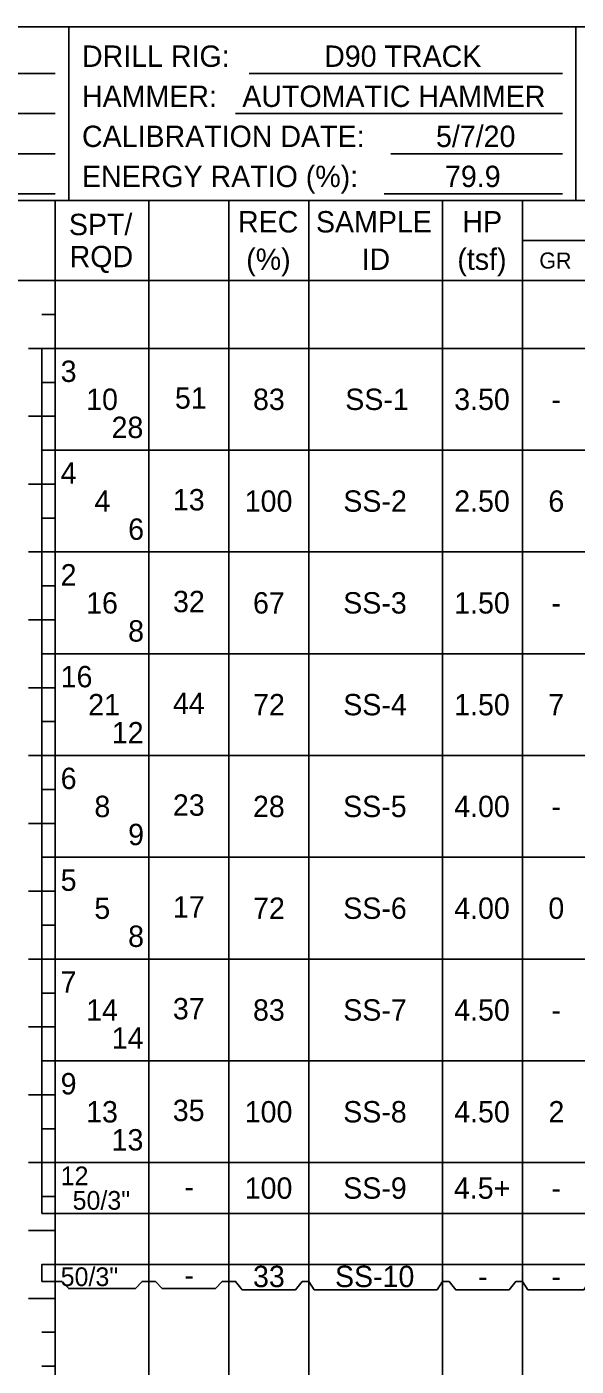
# Model space of a CAD drawing. Extents: x 0 to 0.833, y -0.32 to 0.608.
# Drawn here: x 0.4036 to 0.5751, y 0.1905 to 0.6083 of the extents above; entities that cross this region are included whole.
import ezdxf

# ---------------------------------------------------------------- set-up
doc = ezdxf.new("R2010")
doc.units = 0

msp = doc.modelspace()

# ---------------------------------------------------------------- linework, layer by layer
for points in [[(0, -0.32004), (0.83333, -0.32004), (0.83333, 0.60833), (0, 0.60833)], [(0.40833, 0.47625), (0.4125, 0.47625), (0.4125, 0.508), (0.40833, 0.508)], [(0.40833, 0.4445), (0.4125, 0.4445), (0.4125, 0.47625), (0.40833, 0.47625)], [(0.40833, 0.41275), (0.4125, 0.41275), (0.4125, 0.4445), (0.40833, 0.4445)], [(0.40833, 0.381), (0.4125, 0.381), (0.4125, 0.41275), (0.40833, 0.41275)], [(0.40833, 0.34925), (0.4125, 0.34925), (0.4125, 0.381), (0.40833, 0.381)], [(0.40833, 0.3175), (0.4125, 0.3175), (0.4125, 0.34925), (0.40833, 0.34925)], [(0.40833, 0.28575), (0.4125, 0.28575), (0.4125, 0.3175), (0.40833, 0.3175)], [(0.40833, 0.254), (0.4125, 0.254), (0.4125, 0.28575), (0.40833, 0.28575)], [(0.40833, 0.23812), (0.4125, 0.23812), (0.4125, 0.254), (0.40833, 0.254)], [(0.40833, 0.21696), (0.4125, 0.21696), (0.4125, 0.22225), (0.40833, 0.22225)]]:
    msp.add_lwpolyline(points, close=True)
for points in [[(0.41667, 0.55417), (0.41667, 0.60833)], [(0.575, 0.55417), (0.575, 0.60833)], [(0.32667, 0.59375), (0.4125, 0.59375)], [(0.47305, 0.59375), (0.57083, 0.59375)], [(0.31944, 0.58125), (0.4125, 0.58125)], [(0.46875, 0.58125), (0.57083, 0.58125)], [(0.28403, 0.56875), (0.4125, 0.56875)], [(0.51722, 0.56875), (0.57083, 0.56875)], [(0.2893, 0.55625), (0.4125, 0.55625)], [(0.51514, 0.55625), (0.57083, 0.55625)], [(0, 0.55417), (0.83333, 0.55417)], [(0, 0.55417), (0.83333, 0.55417)], [(0, 0.55417), (0.83333, 0.55417)], [(0, 0.55417), (0.83333, 0.55417)], [(0, 0.55417), (0.83333, 0.55417)], [(0.4125, 0.55417), (0.4125, -0.27517)], [(0.4125, 0.55417), (0.4125, -0.27517)], [(0.44167, 0.55417), (0.44167, -0.27517)], [(0.46667, 0.55417), (0.46667, -0.27517)], [(0.49167, 0.55417), (0.49167, -0.27517)], [(0.53333, 0.55417), (0.53333, -0.27517)], [(0.55833, 0.55417), (0.55833, -0.27517)], [(0.725, 0.54167), (0.55833, 0.54167)], [(0, 0.52917), (0.83333, 0.52917)], [(0, 0.52917), (0.83333, 0.52917)], [(0, 0.52917), (0.83333, 0.52917)], [(0, 0.52917), (0.83333, 0.52917)], [(0, 0.52917), (0.83333, 0.52917)], [(0.4125, 0.51858), (0.40833, 0.51858)], [(0.4125, 0.508), (0.40417, 0.508)], [(0.40833, 0.508), (0.40833, 0.47625)], [(0.40833, 0.508), (0.4125, 0.508)], [(0.4125, 0.508), (0.40833, 0.508)], [(0.4125, 0.508), (0.44167, 0.508)], [(0.44167, 0.508), (0.46667, 0.508)], [(0.46667, 0.508), (0.49167, 0.508)], [(0.49167, 0.508), (0.53333, 0.508)], [(0.53333, 0.508), (0.55833, 0.508)], [(0.55833, 0.508), (0.57917, 0.508)], [(0.4125, 0.49742), (0.40833, 0.49742)], [(0.4125, 0.48683), (0.40417, 0.48683)], [(0.4125, 0.48683), (0.40833, 0.48683)], [(0.40833, 0.47625), (0.4125, 0.47625)], [(0.40833, 0.47625), (0.40833, 0.4445)], [(0.40833, 0.47625), (0.4125, 0.47625)], [(0.4125, 0.47625), (0.40833, 0.47625)], [(0.4125, 0.47625), (0.44167, 0.47625)], [(0.44167, 0.47625), (0.46667, 0.47625)], [(0.46667, 0.47625), (0.49167, 0.47625)], [(0.49167, 0.47625), (0.53333, 0.47625)], [(0.53333, 0.47625), (0.55833, 0.47625)], [(0.55833, 0.47625), (0.57917, 0.47625)], [(0.4125, 0.46567), (0.40417, 0.46567)], [(0.4125, 0.46567), (0.40833, 0.46567)], [(0.4125, 0.45508), (0.40833, 0.45508)], [(0.4125, 0.4445), (0.40417, 0.4445)], [(0.40833, 0.4445), (0.4125, 0.4445)], [(0.40833, 0.4445), (0.40833, 0.41275)], [(0.40833, 0.4445), (0.4125, 0.4445)], [(0.4125, 0.4445), (0.40833, 0.4445)], [(0.4125, 0.4445), (0.44167, 0.4445)], [(0.44167, 0.4445), (0.46667, 0.4445)], [(0.46667, 0.4445), (0.49167, 0.4445)], [(0.49167, 0.4445), (0.53333, 0.4445)], [(0.53333, 0.4445), (0.55833, 0.4445)], [(0.55833, 0.4445), (0.57917, 0.4445)], [(0.4125, 0.43392), (0.40833, 0.43392)], [(0.4125, 0.42333), (0.40417, 0.42333)], [(0.4125, 0.42333), (0.40833, 0.42333)], [(0.40833, 0.41275), (0.4125, 0.41275)], [(0.40833, 0.41275), (0.40833, 0.381)], [(0.40833, 0.41275), (0.4125, 0.41275)], [(0.4125, 0.41275), (0.40833, 0.41275)], [(0.4125, 0.41275), (0.44167, 0.41275)], [(0.44167, 0.41275), (0.46667, 0.41275)], [(0.46667, 0.41275), (0.49167, 0.41275)], [(0.49167, 0.41275), (0.53333, 0.41275)], [(0.53333, 0.41275), (0.55833, 0.41275)], [(0.55833, 0.41275), (0.57917, 0.41275)], [(0.4125, 0.40217), (0.40417, 0.40217)], [(0.4125, 0.40217), (0.40833, 0.40217)], [(0.4125, 0.39158), (0.40833, 0.39158)], [(0.4125, 0.381), (0.40417, 0.381)], [(0.40833, 0.381), (0.4125, 0.381)], [(0.40833, 0.381), (0.40833, 0.34925)], [(0.40833, 0.381), (0.4125, 0.381)], [(0.4125, 0.381), (0.40833, 0.381)], [(0.4125, 0.381), (0.44167, 0.381)], [(0.44167, 0.381), (0.46667, 0.381)], [(0.46667, 0.381), (0.49167, 0.381)], [(0.49167, 0.381), (0.53333, 0.381)], [(0.53333, 0.381), (0.55833, 0.381)], [(0.55833, 0.381), (0.57917, 0.381)], [(0.4125, 0.37042), (0.40833, 0.37042)], [(0.4125, 0.35983), (0.40417, 0.35983)], [(0.4125, 0.35983), (0.40833, 0.35983)], [(0.40833, 0.34925), (0.4125, 0.34925)], [(0.40833, 0.34925), (0.40833, 0.3175)], [(0.40833, 0.34925), (0.4125, 0.34925)], [(0.4125, 0.34925), (0.40833, 0.34925)], [(0.4125, 0.34925), (0.44167, 0.34925)], [(0.44167, 0.34925), (0.46667, 0.34925)], [(0.46667, 0.34925), (0.49167, 0.34925)], [(0.49167, 0.34925), (0.53333, 0.34925)], [(0.53333, 0.34925), (0.55833, 0.34925)], [(0.55833, 0.34925), (0.57917, 0.34925)], [(0.4125, 0.33867), (0.40417, 0.33867)], [(0.4125, 0.33867), (0.40833, 0.33867)], [(0.4125, 0.32808), (0.40833, 0.32808)], [(0.4125, 0.3175), (0.40417, 0.3175)], [(0.40833, 0.3175), (0.4125, 0.3175)], [(0.40833, 0.3175), (0.40833, 0.28575)], [(0.40833, 0.3175), (0.4125, 0.3175)], [(0.4125, 0.3175), (0.40833, 0.3175)], [(0.4125, 0.3175), (0.44167, 0.3175)], [(0.44167, 0.3175), (0.46667, 0.3175)], [(0.46667, 0.3175), (0.49167, 0.3175)], [(0.49167, 0.3175), (0.53333, 0.3175)], [(0.53333, 0.3175), (0.55833, 0.3175)], [(0.55833, 0.3175), (0.57917, 0.3175)], [(0.4125, 0.30692), (0.40833, 0.30692)], [(0.4125, 0.29633), (0.40417, 0.29633)], [(0.4125, 0.29633), (0.40833, 0.29633)], [(0.40833, 0.28575), (0.4125, 0.28575)], [(0.40833, 0.28575), (0.40833, 0.254)], [(0.40833, 0.28575), (0.4125, 0.28575)], [(0.4125, 0.28575), (0.40833, 0.28575)], [(0.4125, 0.28575), (0.44167, 0.28575)], [(0.44167, 0.28575), (0.46667, 0.28575)], [(0.46667, 0.28575), (0.49167, 0.28575)], [(0.49167, 0.28575), (0.53333, 0.28575)], [(0.53333, 0.28575), (0.55833, 0.28575)], [(0.55833, 0.28575), (0.57917, 0.28575)], [(0.4125, 0.27517), (0.40417, 0.27517)], [(0.4125, 0.27517), (0.40833, 0.27517)], [(0.4125, 0.26458), (0.40833, 0.26458)], [(0.4125, 0.254), (0.40417, 0.254)], [(0.40833, 0.254), (0.4125, 0.254)], [(0.40833, 0.254), (0.40833, 0.23812)], [(0.40833, 0.254), (0.4125, 0.254)], [(0.4125, 0.254), (0.40833, 0.254)], [(0.4125, 0.254), (0.44167, 0.254)], [(0.44167, 0.254), (0.46667, 0.254)], [(0.46667, 0.254), (0.49167, 0.254)], [(0.49167, 0.254), (0.53333, 0.254)], [(0.53333, 0.254), (0.55833, 0.254)], [(0.55833, 0.254), (0.57917, 0.254)], [(0.4125, 0.24342), (0.40833, 0.24342)], [(0.40833, 0.23812), (0.4125, 0.23812)], [(0.4125, 0.23812), (0.44167, 0.23812)], [(0.44167, 0.23812), (0.46667, 0.23812)], [(0.46667, 0.23812), (0.49167, 0.23812)], [(0.49167, 0.23812), (0.53333, 0.23812)], [(0.53333, 0.23812), (0.55833, 0.23812)], [(0.55833, 0.23812), (0.57917, 0.23812)], [(0.4125, 0.23283), (0.40417, 0.23283)], [(0.4125, 0.23283), (0.40833, 0.23283)], [(0.40833, 0.22225), (0.40833, 0.21696)], [(0.40833, 0.22225), (0.4125, 0.22225)], [(0.4125, 0.22225), (0.40833, 0.22225)], [(0.4125, 0.22225), (0.44167, 0.22225)], [(0.44167, 0.22225), (0.46667, 0.22225)], [(0.46667, 0.22225), (0.49167, 0.22225)], [(0.49167, 0.22225), (0.53333, 0.22225)], [(0.53333, 0.22225), (0.55833, 0.22225)], [(0.55833, 0.22225), (0.57917, 0.22225)], [(0.40833, 0.21696), (0.4125, 0.21696)], [(0.4125, 0.21696), (0.41458, 0.21696), (0.41667, 0.2147), (0.4375, 0.2147), (0.43958, 0.21696), (0.44167, 0.21696)], [(0.44167, 0.21696), (0.44375, 0.21696), (0.44583, 0.21479), (0.4625, 0.21479), (0.46458, 0.21696), (0.46667, 0.21696)], [(0.46667, 0.21696), (0.46875, 0.21696), (0.47083, 0.21437), (0.4875, 0.21437), (0.48958, 0.21696), (0.49167, 0.21696)], [(0.49167, 0.21696), (0.49333, 0.21437), (0.53167, 0.21437), (0.53333, 0.21696)], [(0.53333, 0.21696), (0.53542, 0.21696), (0.5375, 0.21437), (0.55417, 0.21437), (0.55625, 0.21696), (0.55833, 0.21696)], [(0.55833, 0.21696), (0.56, 0.21437), (0.5775, 0.21437), (0.57917, 0.21696)], [(0.4125, 0.21167), (0.40417, 0.21167)], [(0.4125, 0.21167), (0.40833, 0.21167)], [(0.4125, 0.20108), (0.40833, 0.20108)], [(0.4125, 0.1905), (0.40833, 0.1905)]]:
    msp.add_lwpolyline(points)

# ---------------------------------------------------------------- texts
for s, height, p in [('DRILL RIG:', 0.006667, (0.42083, 0.59583)), ('D90 TRACK', 0.006667, (0.49641, 0.59583)), ('HAMMER:', 0.006667, (0.42083, 0.58333)), ('AUTOMATIC HAMMER', 0.0066667, (0.47086, 0.58333)), ('CALIBRATION DATE:', 0.0066667, (0.42083, 0.57083)), ('5/7/20', 0.006667, (0.53131, 0.57083)), ('ENERGY RATIO (%):', 0.0066667, (0.42083, 0.55833)), ('79.9', 0.006667, (0.53413, 0.55833)), ('SPT/', 0.006667, (0.41673, 0.54333)), ('REC', 0.006667, (0.46952, 0.54417)), ('SAMPLE', 0.006667, (0.49385, 0.54417)), ('HP', 0.006667, (0.53956, 0.54417)), ('RQD', 0.006667, (0.41698, 0.53333)), ('(%)', 0.006667, (0.47209, 0.5325)), ('ID', 0.006667, (0.50809, 0.5325)), ('(tsf)', 0.006667, (0.53798, 0.5325)), ('GR', 0.005, (0.56356, 0.53292)), ('3', 0.00667, (0.41417, 0.49754)), ('10', 0.006667, (0.42213, 0.48879)), ('51', 0.006667, (0.44984, 0.48921)), ('83', 0.006667, (0.4742, 0.48879)), ('SS-1', 0.006667, (0.503, 0.48879)), ('3.50', 0.006667, (0.537, 0.48879)), ('-', 0.00667, (0.56734, 0.48879)), ('28', 0.006667, (0.43006, 0.48004)), ('4', 0.00667, (0.41417, 0.46579)), ('13', 0.006667, (0.4492, 0.45746)), ('100', 0.006667, (0.47162, 0.45704)), ('SS-2', 0.006667, (0.50239, 0.45704)), ('2.50', 0.006667, (0.537, 0.45704)), ('6', 0.00667, (0.56637, 0.45704)), ('4', 0.00667, (0.42472, 0.45704)), ('6', 0.00667, (0.43524, 0.44829)), ('2', 0.00667, (0.41417, 0.43404)), ('16', 0.006667, (0.42212, 0.42529)), ('32', 0.006667, (0.44923, 0.42571)), ('67', 0.006667, (0.4742, 0.42529)), ('SS-3', 0.006667, (0.50236, 0.42529)), ('1.50', 0.006667, (0.537, 0.42529)), ('-', 0.00667, (0.56734, 0.42529)), ('8', 0.00667, (0.43523, 0.41654)), ('16', 0.006667, (0.41417, 0.40229)), ('21', 0.006667, (0.42276, 0.39354)), ('44', 0.006667, (0.44921, 0.39396)), ('72', 0.006667, (0.47423, 0.39354)), ('SS-4', 0.006667, (0.50237, 0.39354)), ('1.50', 0.006667, (0.537, 0.39354)), ('7', 0.00667, (0.56637, 0.39354)), ('12', 0.006667, (0.43014, 0.38479)), ('6', 0.00667, (0.41417, 0.37054)), ('8', 0.00667, (0.4247, 0.36179)), ('23', 0.006667, (0.4492, 0.36221)), ('28', 0.006667, (0.47419, 0.36179)), ('SS-5', 0.006667, (0.50233, 0.36179)), ('4.00', 0.006667, (0.537, 0.36179)), ('-', 0.00667, (0.56734, 0.36179)), ('9', 0.00667, (0.43523, 0.35304)), ('5', 0.00667, (0.41417, 0.33879)), ('5', 0.00667, (0.42468, 0.33004)), ('17', 0.006667, (0.4492, 0.33046)), ('72', 0.006667, (0.47423, 0.33004)), ('SS-6', 0.006667, (0.50236, 0.33004)), ('4.00', 0.006667, (0.537, 0.33004)), ('0', 0.00667, (0.56638, 0.33004)), ('8', 0.00667, (0.43523, 0.32129)), ('7', 0.00667, (0.41417, 0.30704)), ('37', 0.006667, (0.4492, 0.29871)), ('83', 0.006667, (0.4742, 0.29829)), ('SS-7', 0.006667, (0.50236, 0.29829)), ('4.50', 0.006667, (0.537, 0.29829)), ('14', 0.006667, (0.42213, 0.29829)), ('-', 0.00667, (0.56734, 0.29829)), ('14', 0.006667, (0.4301, 0.28954)), ('9', 0.00667, (0.41417, 0.27529)), ('13', 0.006667, (0.42212, 0.26654)), ('35', 0.006667, (0.44917, 0.26696)), ('100', 0.006667, (0.47162, 0.26654)), ('SS-8', 0.006667, (0.50235, 0.26654)), ('4.50', 0.006667, (0.537, 0.26654)), ('2', 0.00667, (0.56641, 0.26654)), ('13', 0.006667, (0.43007, 0.25779)), ('12', 0.005833, (0.41417, 0.24697)), ('100', 0.006667, (0.47162, 0.24273)), ('SS-9', 0.006667, (0.50235, 0.24273)), ('4.5+', 0.006667, (0.5369, 0.24273)), ('50/3"', 0.005833, (0.4179, 0.23932)), ('-', 0.00667, (0.45276, 0.24315)), ('-', 0.00667, (0.56734, 0.24273)), ('50/3"', 0.005833, (0.41417, 0.2155)), ('33', 0.006667, (0.4742, 0.21517)), ('SS-10', 0.006667, (0.49978, 0.21517)), ('-', 0.00667, (0.45276, 0.21558)), ('-', 0.00667, (0.54443, 0.21517)), ('-', 0.00667, (0.56734, 0.21517))]:
    msp.add_text(s, height=height).set_placement(p)

doc.saveas('drawing.dxf')
